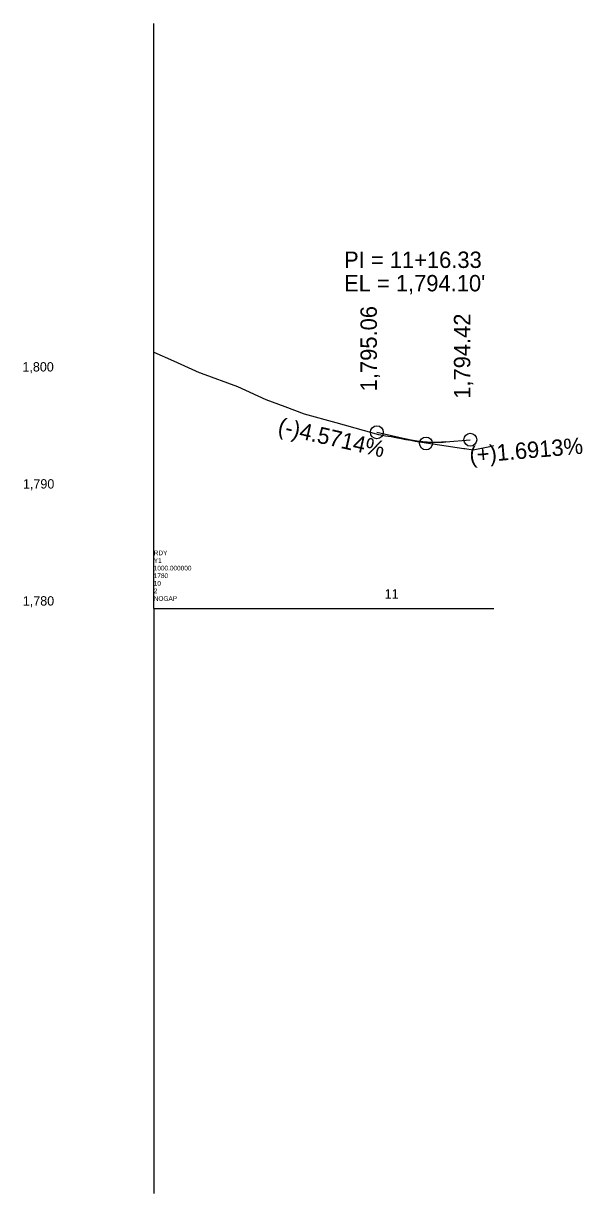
# Model space of a CAD drawing. Extents: x 591243 to 591482, y -49173 to -48673.
import ezdxf

# ---------------------------------------------------------------- set-up
doc = ezdxf.new("R2010")
doc.units = 0
for name, color, linetype in [('Default', 7, 'Continuous'), ('Exist Profile Cell', 7, 'Continuous'), ('Exist Vertical Profile Ground Line', 7, 'Continuous'), ('Prop Vertical Profile Grade', 7, 'Continuous'), ('Prop Vertical Profile Grade Label', 7, 'Continuous'), ('Prop VPI Label', 7, 'Continuous')]:
    doc.layers.add(name, color=color, linetype=linetype)

msp = doc.modelspace()

# ---------------------------------------------------------------- linework, layer by layer
at = {"layer": 'Exist Profile Cell'}
for q in [(591298.37, -48672.62), (591443.7, -48922.62), (591298.37, -49172.62)]:
    msp.add_line((591298.37, -48922.62), q, dxfattribs=at)
at = {"layer": 'Exist Vertical Profile Ground Line'}
msp.add_lwpolyline([(591298.37, -48813.04), (591306.83, -48816.76), (591317.78, -48821.75), (591318.35, -48821.96), (591318.68, -48822.08), (591334.18, -48827.75), (591346.25, -48833.26), (591354.41, -48836.3), (591362.69, -48839.39), (591376.24, -48843.18), (591387.92, -48846.4), (591394.44, -48848.24), (591395.35, -48848.41), (591397.41, -48848.83), (591399.77, -48849.18), (591401.77, -48849.6), (591404.15, -48849.96), (591406.1, -48850.38), (591408.17, -48850.68), (591410.03, -48851.1), (591430.89, -48854.23), (591431.31, -48854.31), (591434.82, -48854.8), (591442.63, -48853.22), (591443.7, -48852.98)], dxfattribs=at)
at = {"layer": 'Prop Vertical Profile Grade'}
for p, q in [((591393.7, -48847.32), (591406.19, -48850.18)), ((591423.2, -48851.41), (591433.62, -48850.52))]:
    msp.add_line(p, q, dxfattribs=at)
msp.add_spline([(591406.19, -48850.18), (591406.53, -48850.26), (591406.87, -48850.33), (591407.21, -48850.4), (591407.55, -48850.47), (591407.89, -48850.54), (591408.23, -48850.61), (591408.57, -48850.67), (591408.91, -48850.73), (591409.25, -48850.79), (591409.59, -48850.85), (591409.93, -48850.91), (591410.27, -48850.96), (591410.61, -48851.01), (591410.95, -48851.06), (591411.29, -48851.11), (591411.63, -48851.15), (591411.97, -48851.19), (591412.32, -48851.23), (591412.66, -48851.27), (591413, -48851.31), (591413.34, -48851.34), (591413.68, -48851.38), (591414.02, -48851.41), (591414.36, -48851.43), (591414.7, -48851.46), (591415.04, -48851.48), (591415.38, -48851.5), (591415.72, -48851.52), (591416.06, -48851.54), (591416.4, -48851.55), (591416.74, -48851.57), (591417.08, -48851.58), (591417.42, -48851.59), (591417.76, -48851.59), (591418.1, -48851.6), (591418.44, -48851.6), (591418.78, -48851.6), (591419.12, -48851.6), (591419.46, -48851.59), (591419.8, -48851.59), (591420.14, -48851.58), (591420.48, -48851.57), (591420.82, -48851.55), (591421.16, -48851.54), (591421.5, -48851.52), (591421.84, -48851.5), (591422.18, -48851.48), (591422.52, -48851.46), (591422.86, -48851.43), (591423.2, -48851.41)], degree=3, dxfattribs=at)
at = {"layer": 'Prop VPI Label'}
for p, q in [((591406.19, -48850.18), (591412.02, -48851.51)), ((591423.2, -48851.41), (591417.44, -48851.89))]:
    msp.add_line(p, q, dxfattribs=at)
for centre in [(591393.7, -48847.32), (591414.7, -48852.12), (591433.62, -48850.52)]:
    msp.add_circle(centre, 2.75, dxfattribs=at)

# ---------------------------------------------------------------- texts
at = {"layer": 'Default'}
for s, p in [('1,800', (591242.29, -48821.37)), ('1,790', (591242.51, -48871.37)), ('11', (591397.04, -48918.37)), ('1,780', (591242.45, -48921.37))]:
    msp.add_text(s, height=4, dxfattribs=at).set_placement(p)
at = {"layer": 'Exist Profile Cell'}
for s, p in [('RDY', (591298.37, -48899.87)), ('Y1', (591298.37, -48903.12)), ('1000.000000', (591298.37, -48906.37)), ('1780', (591298.37, -48909.62)), ('2', (591298.37, -48916.12)), ('10', (591298.37, -48912.87)), ('NOGAP', (591298.37, -48919.37))]:
    msp.add_text(s, height=2, dxfattribs=at).set_placement(p)
at = {"layer": 'Prop Vertical Profile Grade Label'}
for s, rotation, p in [('(-)4.5714%', 347.125, (591351.02, -48847.83)), ('(+)1.6913%', 4.8338, (591433.54, -48860.57))]:
    msp.add_text(s, height=7, rotation=rotation, dxfattribs=at).set_placement(p)
at = {"layer": 'Prop VPI Label'}
for s, p in [('PI = 11+16.33', (591379.7, -48777.12)), ("EL = 1,794.10'", (591379.7, -48787.12))]:
    msp.add_text(s, height=7, dxfattribs=at).set_placement(p)
for s, p in [('1,795.06', (591393.7, -48829.82)), ('1,794.42', (591433.62, -48833.02))]:
    msp.add_text(s, height=7, rotation=90, dxfattribs=at).set_placement(p)

doc.saveas('drawing.dxf')
